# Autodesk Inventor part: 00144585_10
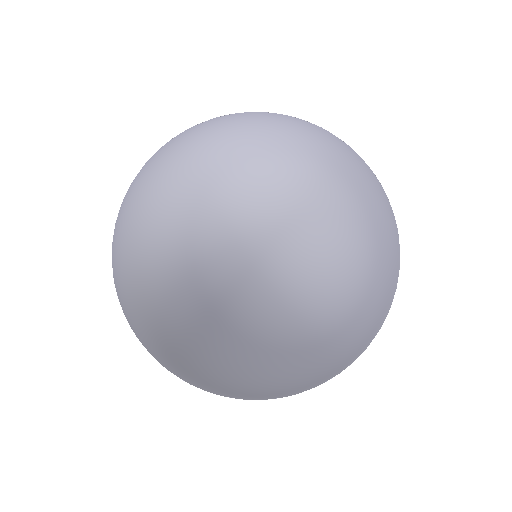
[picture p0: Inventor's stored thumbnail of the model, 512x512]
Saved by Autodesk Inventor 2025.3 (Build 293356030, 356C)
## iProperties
Created: 2021-02
Part Number: 00144585_10
Material: Generico
Document SubType Name: Modeling
Designer: R5800u
Density: 1 g/cm^3
Appearance: Default
Author: TraceParts
Sending System: SolidWorks 2021
Last Author: Albert
Last Saved: 2021-07-28
IsFastener: 1
TYPE: CATASM
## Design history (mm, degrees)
feature "Imported1"
node "Solido1"
